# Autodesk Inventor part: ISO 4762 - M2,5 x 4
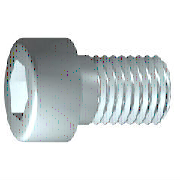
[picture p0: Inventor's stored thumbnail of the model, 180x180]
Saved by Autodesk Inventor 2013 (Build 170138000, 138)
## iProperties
Created: 2012-02
Part Number: ISO 4762 - M2,5 x 4
Material: Edelstahl, 440C
Description: Innensechskantschraube
Document SubType Name: Modeling
Standard: ISO 4762
Designer: rYan
Standard Revision: 1998
Standards Organization: DIN
Language: de-DE
Size Designation: M2,5 x 4
Categories: <MemberInstance><Categories><Category DisplayName="Verbindungselemente" InternalName="e4da775c-781d-43d5-af7c-5136215cf5a6" Mnemonic="FSTN"><Category DisplayNam
Density: 7.75 g/cm^3
IsCustomPart: 0
Author: rYan
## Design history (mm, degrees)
sketch "Skizze1"
  geometry: L1 (-0.733, 0)-(4, 0); L2 (4, 0)-(4, 1.25); L3 (4, 1.25)-(1.125, 1.25); L4 (1.125, 1.25)-(0.849, 1.25); L5 (0.849, 1.25)-(0, 1.25); L6 (0, 1.25)-(0, 2.25); L7 (0, 2.25)-(-2.5, 2.25); L8 (-2.5, 2.25)-(-2.5, 1.155); L9 (-2.5, 1.155)-(-1.4, 1.155); L10 (-1.4, 1.155)-(-0.733, 0); L11 (-3.8, 0)-(5.3, 0) reference; L12 (0, -0.45)-(0, 2.7) reference; L13 (1.125, 1.25)-(0, 1.25)
  constraints: 22 end point, 6 parallel, 2 collinear, 2 perpendicular, 1 horizontal, 1 point on line
  dimensions: "d1" = 2.875 distance from line of L3.end L2 (= GEL); "d2" = 0.27615 distance of L4.end L3.end (computed from GAL); "d3" = 2.5 distance between parallel lines of L8 L6 (= KOH); "d4" = 1.1 distance of L8.end L9.end (= INTI); "d5" = 60 deg angle of L10 L1; "d6" = 2.5 diameter of L3 L1 (= GD); "d7" = 2.5 diameter of L5 L1 (= BDM); "d8" = 2.3094 diameter of L9 L1 (= 1.1547 x SW); "d9" = 4.5 diameter of L7 L1 (= KOD); "d26" = 4 distance between parallel lines of L12 L2 (= NLG)
revolve "Körper" sketch "Skizze1" stored, may be unused: angle "d10" = 90 deg
sketch "Skizze2"
  geometry: L1 (0, -3.15)-(0, 3.15) reference; L2 (-3.15, 0)-(3.15, 0) reference; L3 (1.155, 0)-(0.577, -1); L4 (0.577, -1)-(-0.577, -1); L5 (-0.577, -1)-(-1.155, 0); L6 (-1.155, 0)-(-0.577, 1); L7 (-0.577, 1)-(0.577, 1); L8 (0.577, 1)-(1.155, 0); 2 further points
  constraints: 12 end point, 1 coincident, 1 horizontal alignment, 1 point on line, 12 other
extrude "Loch" join sketch "Skizze2" stored distance "d11" = 10; taper "d12" = 0 deg
workplane "Work Plane1"
fillet "Fillet2" dims "d30" = 0.1 (= R)
body "Solid1"
fillet "Rundung1" dims "d17" = 0.25 (= RR)
feature "Gewinde" dims "d13" = 2.875 (= GEL), "d14" = 0
chamfer "Fase1" distance "d15" = 0.27605 (= -0.5 x SPD + 0.5 x GD); stored, may be unused: second distance "d16" = 0.27605 (= GUL), angle "d27" = 45 deg
other parameters: "GD" = 2.5 [user parameter; used in 2 equation terms], "NLG" = 4 [user parameter; used in 1 equation term], "GEL" = 2.875 [user parameter; used in 2 equation terms], "KOD" = 4.5 [user parameter; used in 1 equation term], "KOH" = 2.5 [user parameter; used in 1 equation term], "INTI" = 1.1 [user parameter; used in 1 equation term], "GAL" = 0.27605 (= 0.61345 x PTC) [user parameter; used in 1 equation term], "GUL" = 0.27605 (= 0.61345 x PTC) [user parameter; used in 1 equation term], "BDM" = 2.5 (= NND) [user parameter; used in 1 equation term], "SW" = 2 [user parameter; used in 2 equation terms], "RR" = 0.25 [user parameter; used in 1 equation term], "SPD" = 1.94789 (= NND - 1.2269 x PTC) [user parameter; used in 1 equation term], "d19" = 0, "d28" = 0, "d29" = 0, "R" = 0.1 [user parameter; used in 1 equation term], "TOA" = 30 deg [user parameter], "GD1" = 1.94789 (= THREADDIA - 1.2269 x PTC) [user parameter], "THREADDIA" = 2.5 [user parameter; used in 1 equation term], "FAWI" = 45 deg [user parameter], "TPU" = 22.22222 (computed from PTC) [user parameter], "PTC" = 0.45 [user parameter; used in 5 equation terms], "NND" = 2.5 [user parameter; used in 2 equation terms], "E0" = 2.31 (= 1.155 x SW) [user parameter]
